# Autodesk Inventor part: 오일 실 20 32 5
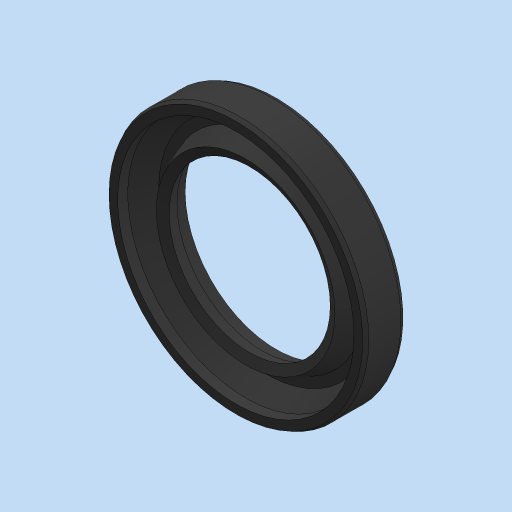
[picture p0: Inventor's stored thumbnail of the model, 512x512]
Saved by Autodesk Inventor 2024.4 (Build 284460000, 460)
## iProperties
Created: 2026-07
Part Number: 오일 실 20 32 5
Material: 고무
Description: 오일 실 - 스프링 장착, 비스프링, 고무 덮개 G
Document SubType Name: Modeling
Designer: home
Density: 0.93 g/cm^3
Appearance: 기본값
Author: jhkim
Sending System: Autodesk Inventor 2027
Preprocessor: ST-DEVELOPER v20.1
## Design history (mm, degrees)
feature "Solid1"
node "솔리드1"
